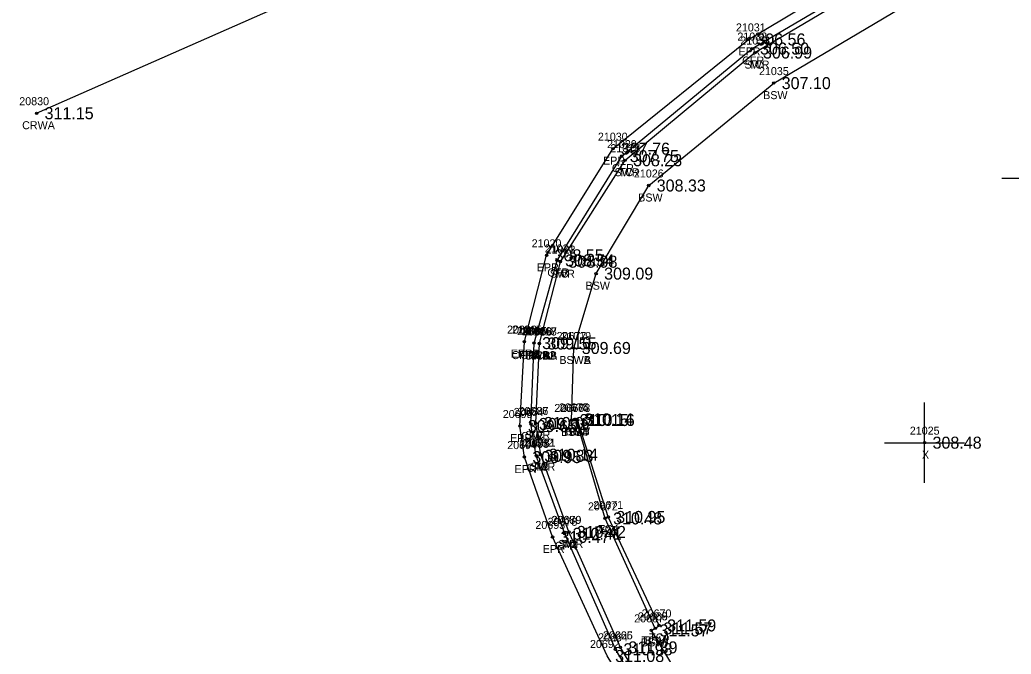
# Model space of a CAD drawing. Extents: x 1970242 to 1971082, y 803104 to 803947.
# Drawn here: x 1970621.9 to 1970745.8, y 803521.5 to 803600.7 of the extents above; entities that cross this region are included whole.
import ezdxf

# ---------------------------------------------------------------- set-up
doc = ezdxf.new("R2010")
doc.units = 0
for name, color, linetype in [('RD_DTM_BkLn1', 7, 'Continuous'), ('RD_DTM_BkLn2', 7, 'Continuous'), ('RD_EX_Conc', 7, 'Continuous'), ('RD_EX_Conc_txCode', 7, 'Continuous'), ('RD_EX_Misc', 7, 'Continuous'), ('RD_EX_Misc_txCode', 7, 'Continuous'), ('RD_EX_Road', 7, 'Continuous'), ('RD_EX_Road_txCode', 7, 'Continuous'), ('RD_EX_TX_Conc_ELEV', 7, 'Continuous'), ('RD_EX_TX_Misc_ELEV', 7, 'Continuous'), ('RD_EX_TX_Road_ELEV', 7, 'Continuous'), ('RD_HC_Survey_ELEV', 7, 'Continuous'), ('RD_HC_Survey_txCode', 7, 'Continuous'), ('RD_SMD_Locator', 7, 'Continuous')]:
    doc.layers.add(name, color=color, linetype=linetype)

msp = doc.modelspace()

# ---------------------------------------------------------------- linework, layer by layer
at = {"layer": 'RD_DTM_BkLn1'}
msp.add_lwpolyline([(1970624.03, 803589.05), (1970677.08, 803612.45), (1970725.69, 803632.88), (1970818.37, 803667.22), (1970910.82, 803701.07)], dxfattribs=at)
at = {"layer": 'RD_DTM_BkLn2'}
for points in [[(1970686.87, 803560.28), (1970689.49, 803570.5), (1970697.58, 803583.18), (1970713.81, 803596.63), (1970735.37, 803609.4), (1970825.99, 803648.95), (1970831.2, 803650.84), (1970835.92, 803652.69), (1970844.52, 803655.97), (1970849.28, 803657.82)], [(1970822.14, 803392.47), (1970810.28, 803402.9), (1970754.12, 803456.32), (1970718.38, 803492.24), (1970714.88, 803495.79), (1970706.38, 803506.76), (1970696.99, 803522.32), (1970690.55, 803536.74), (1970687.04, 803546.39), (1970686.42, 803550.35), (1970686.87, 803560.28)], [(1970701.35, 803524.69), (1970701.83, 803525.06), (1970695.47, 803538.61), (1970691.65, 803550.73), (1970691.46, 803550.8)]]:
    msp.add_lwpolyline(points, dxfattribs=at)
at = {"layer": 'RD_EX_Conc'}
for points in [[(1970686.21, 803560.33), (1970689.09, 803570.66), (1970697.16, 803583.69), (1970713.44, 803597.13), (1970734.87, 803609.74), (1970825.69, 803649.6), (1970830.95, 803651.58)], [(1970686.87, 803560.28), (1970689.49, 803570.5), (1970697.58, 803583.18), (1970713.81, 803596.63), (1970735.37, 803609.4), (1970825.99, 803648.95), (1970831.2, 803650.84)], [(1970691.16, 803559.72), (1970693.96, 803569.01), (1970700.53, 803580.02), (1970716.15, 803592.81), (1970737.19, 803605.29), (1970827.17, 803644.49), (1970832.63, 803646.72), (1970831.2, 803650.84)], [(1970714.25, 803495.32), (1970705.81, 803506.24), (1970696.37, 803522.08), (1970690.03, 803536.51), (1970686.48, 803546.25), (1970685.81, 803550.23), (1970686.21, 803560.33)], [(1970717.93, 803498.84), (1970714.88, 803495.79), (1970706.38, 803506.76), (1970696.99, 803522.32), (1970690.55, 803536.74), (1970687.04, 803546.39), (1970686.42, 803550.35), (1970686.87, 803560.28)], [(1970717.93, 803498.84), (1970710.12, 803509.16), (1970700.87, 803524.44), (1970701.35, 803524.69), (1970695.08, 803538.43), (1970691.46, 803550.8), (1970690.9, 803550.72), (1970691.16, 803559.72)]]:
    msp.add_lwpolyline(points, dxfattribs=at)
at = {"layer": 'RD_EX_Misc'}
for p, q in [((1970744.66, 803580.95), (1970754.66, 803580.95)), ((1970735, 803542.89), (1970735, 803552.89)), ((1970730, 803547.89), (1970740, 803547.89))]:
    msp.add_line(p, q, dxfattribs=at)
at = {"layer": 'RD_EX_Road'}
msp.add_lwpolyline([(1970707.08, 803502.25), (1970704.83, 803505.7), (1970695.33, 803521.24), (1970688.51, 803536.11), (1970684.99, 803546.09), (1970684.43, 803549.97), (1970685, 803560.52), (1970685, 803560.52), (1970687.77, 803571.3), (1970696.05, 803584.62), (1970712.98, 803598.27), (1970734.15, 803610.93), (1970825.09, 803650.42), (1970830.48, 803652.5), (1970835.31, 803654.39), (1970843.69, 803657.88), (1970848.64, 803660), (1970849.95, 803660.12), (1970917.12, 803684.38)], dxfattribs=at)
at = {"layer": 'RD_SMD_Locator'}
for centre in [(1970712.98, 803598.27), (1970713.44, 803597.13), (1970713.81, 803596.63), (1970713.81, 803596.63), (1970716.15, 803592.81), (1970624.03, 803589.05), (1970696.05, 803584.62), (1970697.16, 803583.69), (1970697.58, 803583.18), (1970697.58, 803583.18), (1970700.53, 803580.02), (1970687.77, 803571.3), (1970689.09, 803570.66), (1970689.49, 803570.5), (1970689.49, 803570.5), (1970693.96, 803569.01), (1970685, 803560.52), (1970685, 803560.52), (1970686.21, 803560.33), (1970686.21, 803560.33), (1970686.87, 803560.28), (1970686.87, 803560.28), (1970686.87, 803560.28), (1970686.87, 803560.28), (1970691.16, 803559.72), (1970691.16, 803559.72), (1970684.43, 803549.97), (1970685.81, 803550.23), (1970686.42, 803550.35), (1970686.42, 803550.35), (1970690.9, 803550.72), (1970691.46, 803550.8), (1970691.46, 803550.8), (1970691.65, 803550.73), (1970735, 803547.89), (1970686.48, 803546.25), (1970687.04, 803546.39), (1970687.04, 803546.39), (1970684.99, 803546.09), (1970695.08, 803538.43), (1970695.47, 803538.61), (1970690.03, 803536.51), (1970690.55, 803536.74), (1970690.55, 803536.74), (1970688.51, 803536.11), (1970701.83, 803525.06), (1970700.87, 803524.44), (1970701.35, 803524.69), (1970701.35, 803524.69), (1970696.37, 803522.08), (1970696.99, 803522.32), (1970696.99, 803522.32)]:
    msp.add_circle(centre, 0.15, dxfattribs=at)

# ---------------------------------------------------------------- texts
at = {"layer": 'RD_EX_Conc_txCode'}
for s, p in [('21032', (1970711.61, 803598.13)), ('21033', (1970711.98, 803597.63)), ('21034', (1970711.98, 803597.63)), ('CFR', (1970712.21, 803595.13)), ('SWR', (1970712.5, 803594.63)), ('TC', (1970713.02, 803594.63)), ('21035', (1970714.31, 803593.81)), ('BSW', (1970714.83, 803590.81)), ('21029', (1970695.32, 803584.69)), ('21027', (1970695.74, 803584.18)), ('21028', (1970695.74, 803584.18)), ('CFR', (1970695.93, 803581.69)), ('SWR', (1970696.26, 803581.18)), ('TC', (1970696.78, 803581.18)), ('21026', (1970698.68, 803581.02)), ('BSW', (1970699.22, 803578.02)), ('21021', (1970687.54, 803571.66)), ('21022', (1970687.66, 803571.5)), ('21023', (1970687.66, 803571.5)), ('21024', (1970692.12, 803570.01)), ('CFR', (1970687.86, 803568.66)), ('SWR', (1970688.18, 803568.5)), ('TC', (1970688.7, 803568.5)), ('BSW', (1970692.64, 803567.01)), ('20685', (1970684.07, 803561.33)), ('21016', (1970684.64, 803561.33)), ('20688', (1970684.73, 803561.28)), ('20689', (1970684.73, 803561.28)), ('21017', (1970685.32, 803561.28)), ('21018', (1970685.32, 803561.28)), ('20677', (1970689.02, 803560.72)), ('21019', (1970689.61, 803560.72)), ('CFRA 12', (1970683.39, 803558.33)), ('CFRB', (1970684.51, 803558.33)), ('SWRA', (1970685.06, 803558.28)), ('SWRB', (1970685.08, 803558.28)), ('TCA', (1970685.58, 803558.28)), ('TCB', (1970685.6, 803558.28)), ('BSWA', (1970689.36, 803557.72)), ('BSWB', (1970689.37, 803557.72)), ('20676', (1970688.73, 803551.72)), ('20674', (1970689.32, 803551.8)), ('20675', (1970689.32, 803551.8)), ('20673', (1970689.51, 803551.73)), ('20684', (1970683.67, 803551.23)), ('20686', (1970684.26, 803551.35)), ('20687', (1970684.28, 803551.35)), ('CFR', (1970684.58, 803548.23)), ('SWR', (1970685.11, 803548.35)), ('TC', (1970685.63, 803548.35)), ('BSW', (1970689.58, 803548.72)), ('TC4B', (1970689.74, 803548.8)), ('BSW', (1970690.14, 803548.8)), ('TC4', (1970690.4, 803548.73)), ('20683', (1970684.34, 803547.25)), ('20682', (1970684.9, 803547.39)), ('20681', (1970685.18, 803547.39)), ('CFR', (1970685.26, 803544.25)), ('SWR', (1970685.73, 803544.39)), ('TC', (1970686.25, 803544.39)), ('20672', (1970692.94, 803539.43)), ('20671', (1970693.61, 803539.61)), ('20678', (1970687.89, 803537.51)), ('20680', (1970688.37, 803537.74)), ('20679', (1970688.41, 803537.74)), ('TC4', (1970694.23, 803536.61)), ('BSW', (1970693.76, 803536.43)), ('CFR', (1970688.8, 803534.51)), ('SWR', (1970689.24, 803534.74)), ('TC', (1970689.76, 803534.74)), ('20667', (1970698.71, 803525.44)), ('20668', (1970699.18, 803525.69)), ('20669', (1970699.18, 803525.69)), ('20670', (1970699.65, 803526.06)), ('20664', (1970694.2, 803523.08)), ('20666', (1970694.8, 803523.32)), ('20665', (1970694.82, 803523.32)), ('TC4', (1970700.58, 803523.06)), ('TC4A', (1970699.61, 803522.69)), ('BSW', (1970699.56, 803522.44)), ('BSW', (1970700.03, 803522.69))]:
    msp.add_text(s, height=1, dxfattribs=at).set_placement(p)
at = {"layer": 'RD_EX_Misc_txCode'}
for s, p in [('21025', (1970733.16, 803548.89)), ('X', (1970734.68, 803545.89))]:
    msp.add_text(s, height=1, dxfattribs=at).set_placement(p)
at = {"layer": 'RD_EX_Road_txCode'}
for s, p in [('21031', (1970711.43, 803599.27)), ('EPR', (1970711.75, 803596.27)), ('21030', (1970694.18, 803585.62)), ('EPR', (1970694.82, 803582.62)), ('21020', (1970685.9, 803572.3)), ('EPR', (1970686.54, 803569.3)), ('20696', (1970682.83, 803561.52)), ('21015', (1970683.45, 803561.52)), ('EPRA', (1970683.28, 803558.52)), ('EPRB', (1970683.3, 803558.52)), ('20695', (1970682.29, 803550.97)), ('EPR', (1970683.2, 803547.97)), ('20694', (1970682.85, 803547.09)), ('EPR', (1970683.76, 803544.09)), ('20693', (1970686.37, 803537.11)), ('EPR', (1970687.28, 803534.11)), ('20692', (1970693.19, 803522.24))]:
    msp.add_text(s, height=1, dxfattribs=at).set_placement(p)
at = {"layer": 'RD_EX_TX_Conc_ELEV'}
for s, p in [('306.50', (1970714.44, 803596.38)), ('306.99', (1970714.81, 803595.88)), ('306.99', (1970714.81, 803595.88)), ('307.10', (1970717.15, 803592.06)), ('307.75', (1970698.16, 803582.94)), ('308.23', (1970698.58, 803582.43)), ('308.23', (1970698.58, 803582.43)), ('308.33', (1970701.53, 803579.27)), ('308.54', (1970690.09, 803569.91)), ('308.98', (1970690.49, 803569.75)), ('308.98', (1970690.49, 803569.75)), ('309.09', (1970694.96, 803568.26)), ('309.10', (1970687.21, 803559.58)), ('309.10', (1970687.21, 803559.58)), ('309.55', (1970687.87, 803559.53)), ('309.55', (1970687.87, 803559.53)), ('309.55', (1970687.87, 803559.53)), ('309.55', (1970687.87, 803559.53)), ('309.69', (1970692.16, 803558.97)), ('309.69', (1970692.16, 803558.97)), ('310.15', (1970691.9, 803549.97)), ('310.14', (1970692.46, 803550.05)), ('310.14', (1970692.46, 803550.05)), ('310.16', (1970692.65, 803549.98)), ('309.61', (1970686.81, 803549.48)), ('310.07', (1970687.42, 803549.6)), ('310.07', (1970687.42, 803549.6)), ('309.83', (1970687.48, 803545.5)), ('310.14', (1970688.04, 803545.64)), ('310.14', (1970688.04, 803545.64)), ('310.48', (1970696.08, 803537.68)), ('310.95', (1970696.47, 803537.86)), ('310.41', (1970691.03, 803535.76)), ('310.42', (1970691.55, 803535.99)), ('310.42', (1970691.55, 803535.99)), ('311.57', (1970701.87, 803523.69)), ('311.57', (1970702.35, 803523.94)), ('311.57', (1970702.35, 803523.94)), ('311.59', (1970702.83, 803524.31)), ('310.98', (1970697.37, 803521.33)), ('311.39', (1970697.99, 803521.57)), ('311.39', (1970697.99, 803521.57))]:
    msp.add_text(s, height=1.5, dxfattribs=at).set_placement(p)
at = {"layer": 'RD_EX_TX_Misc_ELEV'}
msp.add_text('308.48', height=1.5, dxfattribs=at).set_placement((1970736, 803547.14))
at = {"layer": 'RD_EX_TX_Road_ELEV'}
for s, p in [('306.56', (1970713.98, 803597.52)), ('307.76', (1970697.05, 803583.87)), ('308.55', (1970688.77, 803570.55)), ('309.09', (1970686, 803559.77)), ('309.09', (1970686, 803559.77)), ('309.65', (1970685.43, 803549.22)), ('309.95', (1970685.99, 803545.34)), ('310.47', (1970689.51, 803535.36)), ('311.08', (1970696.33, 803520.49))]:
    msp.add_text(s, height=1.5, dxfattribs=at).set_placement(p)
at = {"layer": 'RD_HC_Survey_ELEV'}
msp.add_text('311.15', height=1.5, dxfattribs=at).set_placement((1970625.03, 803588.3))
at = {"layer": 'RD_HC_Survey_txCode'}
for s, p in [('20830', (1970621.87, 803590.05)), ('CRWA', (1970622.23, 803587.05))]:
    msp.add_text(s, height=1, dxfattribs=at).set_placement(p)

doc.saveas('drawing.dxf')
